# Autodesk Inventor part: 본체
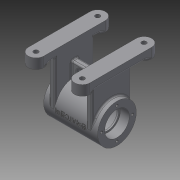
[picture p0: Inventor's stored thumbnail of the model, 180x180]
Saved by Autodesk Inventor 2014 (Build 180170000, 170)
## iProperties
Created: 2015-11
Part Number: 본체
Material: Generic
Document SubType Name: Modeling
Designer: user
Density: 1 g/cm^3
Appearance: Default
Author: user
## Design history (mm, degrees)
sketch "Sketch1"
  geometry: L1 (0, 0)-(20, 0); L2 (20, 0)-(20, 80); L3 (20, 80)-(0, 80); L4 (0, 80)-(0, 0); L5 (60, 80)-(80, 80); L6 (80, 80)-(80, 0); L7 (80, 0)-(60, 0); L8 (60, 0)-(60, 80)
  constraints: 16 end point, 4 parallel, 2 equal length, 2 horizontal, 2 perpendicular, 1 collinear
  dimensions: "d0" = 80 distance of L3.end L1.start; "d1" = 20 distance of L2.end L3.end; "d2" = 80 distance between parallel lines of L6 L4
extrude "Extrusion1" new body sketch "Sketch1" distance "d3" = 10; taper "d4" = 0 deg
sketch "Sketch2"
  geometry: L1 (20, 0)-(20, 80) reference; L2 (80, 0)-(80, 80) reference; C1 r 10 at (10, 0); C2 r 10 at (70, 0); 1 further point
  constraints: 2 centre point
  dimensions: "d5" = 20 diameter of C1; "d6" = 10 distance from line of L1 C1.centre; "d7" = 20 diameter of C2; "d8" = 10 distance from line of L2 C2.centre
extrude "Extrusion2" join sketch "Sketch2" distance "d9" = 13; taper "d10" = 0 deg
workplane "Work Plane1"
mirror "Mirror1"
workplane "Work Plane2"
sketch "Sketch3"
  geometry: L1 (0, 10)-(80, 10) reference; L2 (90, -3)-(90, 10) reference; C1 r 25 at (40, -58); 1 further point
  constraints: 1 centre point
  dimensions: "d13" = 50 diameter of C1; "d14" = 68 distance from line of L1 C1.centre; "d15" = 50 distance from line of L2 C1.centre
extrude "Extrusion3" join sketch "Sketch3" distance "d16" = 70; taper "d17" = 0 deg
sketch "Sketch4"
  geometry: L1 (-60, 80)-(-60, 0) reference; L2 (-80, 0)-(-80, 80) reference; L3 (0, 80)-(0, 0) reference; L4 (-20, 0)-(-20, 80) reference; L5 (-60, 15)-(-68, 15); L6 (-68, 15)-(-68, 65); L7 (-68, 65)-(-60, 65); L8 (-20, 65)-(-12, 65); L9 (-12, 65)-(-12, 15); L10 (-12, 15)-(-20, 15); L11 (-20, 65)-(-20, 15); L12 (-60, 65)-(-60, 15); A1 r 10 centre (-70, 0) between (-80, 0) and (-60, 0) reference; A2 r 10 centre (-70, 80) between (-60, 80) and (-80, 80) reference; A3 r 10 centre (-10, 0) between (-20, 0) and (0, 0) reference; A4 r 10 centre (-10, 80) between (0, 80) and (-20, 80) reference; 1 further point
  constraints: 16 end point, 5 perpendicular, 4 point on line, 3 collinear
  dimensions: "d18" = 8 distance between parallel lines of L12 L6; "d19" = 8 distance between parallel lines of L9 L11; "d20" = 50 distance of L5.end L6.end; "d21" = 50 distance of L8.end L9.end; "d22" = 15 distance from line of A1.centre L5; "d23" = 15 distance from line of A3.centre L10
extrude "Extrusion4" join sketch "Sketch4" stored distance "d24" = 70; taper "d25" = 0 deg
workplane "Work Plane3"
sketch "Sketch5"
  geometry: L1 (75, 15)-(75, 65) reference; L2 (12, 65)-(20, 65) reference; L3 (20, 65)-(20, 15) reference; L4 (12, 15)-(20, 15) reference; L5 (12, 15)-(12, 65) reference; L6 (5, 65)-(5, 15) reference; L7 (60, 15)-(68, 15) reference; L8 (60, 15)-(60, 65) reference; L9 (60, 65)-(68, 65) reference; L10 (68, 65)-(68, 15) reference; C1 r 5 at (40, 40); 1 further point
  constraints: 1 centre point
  dimensions: "d27" = 10 diameter of C1; "d36" = 25 distance from line of C1.centre L7; "d76" = 35 distance from line of C1.centre L1
extrude "Extrusion5" join sketch "Sketch5" stored distance "d28" = 70; taper "d29" = 0 deg
workplane "Work Plane4"
sketch "Sketch6"
  geometry: L1 (60, 15)-(68, 15) reference; L2 (60, 15)-(60, 65) reference; L3 (60, 65)-(68, 65) reference; L4 (68, 65)-(68, 15) reference; L5 (5, 65)-(5, 15) reference; L6 (12, 65)-(20, 65) reference; L7 (20, 65)-(20, 15) reference; L8 (12, 15)-(20, 15) reference; L9 (12, 15)-(12, 65) reference; L10 (75, 15)-(75, 65) reference; L11 (20, 44)-(60, 44); L12 (60, 44)-(60, 36); L13 (60, 36)-(20, 36); L14 (20, 36)-(20, 44); 3 further points
  constraints: 8 end point, 2 collinear, 2 parallel, 1 horizontal, 1 midpoint, 1 perpendicular, 1 other
  dimensions: "d32" = 25 distance from line of L3 point (60, 40); "d33" = 8 distance of L13.end L11.start
extrude "Extrusion6" join sketch "Sketch6" stored distance "d34" = 70; taper "d35" = 0 deg
sketch "Sketch7"
  geometry: L1 (12, 10)-(28, 10); L2 (12, 6.5)-(28, 6.5); L3 (28, 13.5)-(12, 13.5); L4 (40, -23)-(60, -23) reference; L5 (-15, 70)-(-15, 20) reference; A1 r 3.5 centre (12, 10) between (12, 13.5) and (12, 6.5); A2 r 3.5 centre (28, 10) between (28, 6.5) and (28, 13.5); 2 further points
  constraints: 8 end point, 4 point on circle, 4 tangent, 2 centre point, 1 horizontal, 1 midpoint, 1 parallel
  dimensions: "d37" = 3.5 radius of A2; "d38" = 33 distance from line of L4 point (20, 10); "d40" = 23 dimension on A2 A1; "d41" = 35 distance from line of point (20, 10) L5
extrude "Extrusion7" cut sketch "Sketch7" stored distance "d42" = 70; taper "d43" = 0 deg
hole "Hole1" diameter "d46" = 28; stored, may be unused: countersink angle "d50" = 90 deg, drill point angle "d52" = 0 deg; dims "d47" = 6, "d48" = 32, "d49" = 12, "d51" = 14, "d53" = 10, "d54" = 10
workplane "Work Plane5"
mirror "Mirror2"
workplane "Work Plane6"
sketch "Sketch8"
  geometry: C1 r 21 at (0, 0); 1 further point
  constraints: 1 centre point
  dimensions: "d56" = 42 diameter of C1
extrude "Extrusion8" cut sketch "Sketch8" distance "d57" = 42; taper "d58" = 0 deg
sketch "Sketch9"
  geometry: 2 further points
hole "Hole2" sketch "Sketch9" at (-20, 0) diameter "d60" = 3.242; stored, may be unused: countersink angle "d64" = 90 deg, drill point angle "d66" = 118 deg; dims "d61" = 8, "d62" = 4, "d63" = 8, "d65" = 10
pattern_circular "Circular Pattern1" dims angle "d68" = 360 deg
workplane "Work Plane7"
mirror "Mirror3"
workplane "Work Plane9"
  workplane "Work Plane8"
sketch "Sketch10"
  geometry: L1 (-7, -83)-(63, -83) reference; L2 (63, -83)-(63, -33) reference; 3 further points
  constraints: 1 other
  dimensions: "d77" = 25 distance from line of point (28, -58) L1; "d78" = 35 distance from line of point (28, -58) L2
emboss "Emboss1" sketch "Sketch10" dims "d9" = 13, "d10" = 0, "d79" = 0.5, "d80" = 0
hole "Hole3" diameter "d83" = 6; stored, may be unused: countersink angle "d87" = 90 deg, drill point angle "d89" = 0 deg; dims "d84" = 6, "d85" = 4, "d86" = 8, "d88" = 10, "d90" = 10, "d91" = 10
workplane "Work Plane11"
sketch "Sketch11"
  geometry: L1 (-58, 25)-(-33.751, 39); L2 (-58, 25)-(-30, 25); C1 r 14 at (-58, 25) reference; 1 further point
  constraints: 4 end point, 1 equal length, 1 horizontal
  dimensions: "d92" = 28 distance of L1.start L1.end; "d93" = 30 deg angle of L2 L1
workplane "Work Plane12"
sketch "Sketch12"
  geometry: L1 (0, 0)-(28, 0) reference; L2 (28, 0)-(22.856, 0); L3 (22.856, 0)-(22.856, 6); L4 (22.856, 6)-(28, 6); L5 (28, 6)-(28, 0); 1 further point
  constraints: 8 end point, 2 parallel, 1 horizontal, 1 perpendicular
  dimensions: "d95" = 6 distance of L2.end L3.end
revolve "Revolution1" sketch "Sketch12" stored, may be unused: angle "d96" = 90 deg
hole "Hole4" diameter "d99" = 6; stored, may be unused: countersink angle "d103" = 90 deg, drill point angle "d105" = 0 deg; dims "d97" = 10, "d98" = 10, "d100" = 6, "d101" = 12, "d102" = 4, "d104" = 10
pattern_linear "Rectangular Pattern1" dims "d112" = 60
fillet "Fillet1" dims "d106" = 0.3
chamfer "Chamfer1" distance "d107" = 1; stored, may be unused: second distance "d108" = 2, angle "d109" = 45 deg
fillet "Fillet2" dims "d116" = 3.5
fillet "Fillet3" dims "d117" = 3
fillet "Fillet4" dims "d118" = 2
fillet "Fillet5" dims "d119" = 2
fillet "Fillet6" dims "d120" = 2
fillet "Fillet7" dims "d121" = 0.3
hole "Hole5" diameter "d124" = 4.917; stored, may be unused: countersink angle "d128" = 90 deg, drill point angle "d130" = 0 deg; dims "d122" = 10, "d123" = 10, "d125" = 13, "d126" = 12, "d127" = 4, "d129" = 13
body "Solid1"
node "Projected Loop1"
node "Projected Loop2"
node "Projected Loop3"
node "Projected Loop4"
other parameters: "d12" = 5, "d26" = -96, "d30" = -23, "d55" = -14, "d73" = 25.5, "d94" = 90 deg
